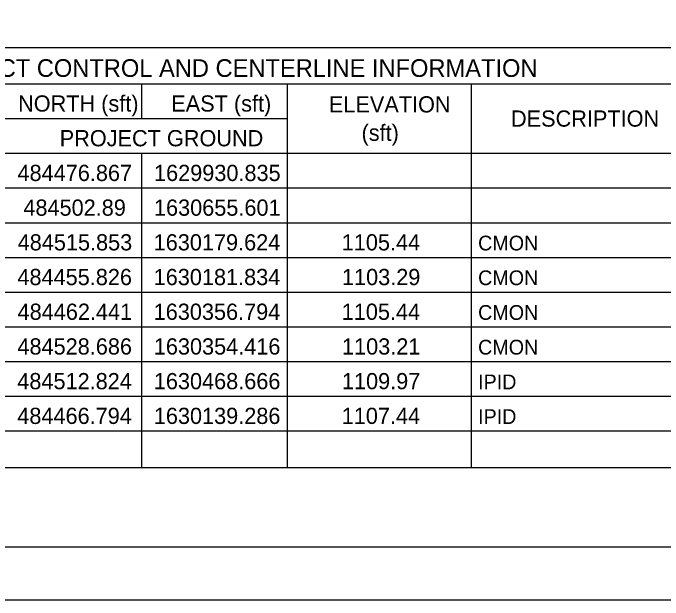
# Model space of a CAD drawing. Extents: x 0 to 34, y 0 to 22.
# Drawn here: x 24.66 to 30.83, y 0 to 5.57 of the extents above; entities that cross this region are included whole.
import ezdxf

# ---------------------------------------------------------------- set-up
doc = ezdxf.new("R2010")
doc.units = 0
for name, color, linetype in [('SH_Border', 7, 'Continuous'), ('SH_Cut_Line', 7, 'Continuous'), ('SH_Data', 7, 'Continuous'), ('SH_Text', 7, 'Continuous')]:
    doc.layers.add(name, color=color, linetype=linetype)

msp = doc.modelspace()

# ---------------------------------------------------------------- linework, layer by layer
at = {"layer": 'SH_Border'}
msp.add_lwpolyline([(1.5, 21.5), (33.5, 21.5), (33.5, 0.5), (1.5, 0.5)], close=True, dxfattribs=at)
at = {"layer": 'SH_Cut_Line'}
msp.add_lwpolyline([(0, 0), (34, 0), (34, 22), (0, 22)], close=True, dxfattribs=at)
at = {"layer": 'SH_Data'}
for p, q in [((20.5456, 5.2448), (30.9386, 5.2448)), ((20.5456, 4.8989), (30.9386, 4.8989)), ((25.8821, 4.8989), (25.8821, 4.5695)), ((27.2656, 4.8989), (27.2656, 1.2589)), ((29.0115, 4.8989), (29.0115, 1.2589)), ((21.2868, 4.5695), (27.2656, 4.5695)), ((20.5456, 4.2401), (30.9386, 4.2401)), ((25.8821, 4.2401), (25.8821, 1.2589)), ((20.5456, 3.9107), (30.9386, 3.9107)), ((20.5456, 3.5812), (30.9386, 3.5812)), ((20.5456, 3.2518), (30.9386, 3.2518)), ((20.5456, 2.9224), (30.9386, 2.9224)), ((20.5456, 2.593), (30.9386, 2.593)), ((20.5456, 2.2636), (30.9386, 2.2636)), ((20.5456, 1.9342), (30.9386, 1.9342)), ((20.5456, 1.6048), (30.9386, 1.6048)), ((20.5456, 1.2589), (30.9386, 1.2589))]:
    msp.add_line(p, q, dxfattribs=at)

# ---------------------------------------------------------------- texts
at = {"layer": 'SH_Text'}
for s, height, p in [('PRIMARY PROJECT CONTROL AND CENTERLINE INFORMATION', 0.168, (22.6895, 4.9648)), ('NORTH (sft)', 0.154, (24.7085, 4.6354)), ('EAST (sft)', 0.154, (26.1633, 4.6354)), ('ELEVATION ', 0.154, (27.6603, 4.6272)), ('DESCRIPTION', 0.154, (29.3901, 4.4925)), ('(sft)', 0.154, (27.9706, 4.3577)), ('PROJECT GROUND', 0.154, (25.1039, 4.306)), ('484476.867', 0.154, (24.7029, 3.9765)), ('1629930.835', 0.154, (25.9996, 3.9765)), ('484502.89', 0.154, (24.7588, 3.6471)), ('1630655.601', 0.154, (25.9991, 3.6471)), ('484515.853', 0.154, (24.7046, 3.3177)), ('1630179.624', 0.154, (25.9963, 3.3177)), ('1105.44', 0.154, (27.7823, 3.3177)), ('CMON', 0.14, (29.0774, 3.3177)), ('484455.826', 0.154, (24.7022, 2.9883)), ('1630181.834', 0.154, (25.9963, 2.9883)), ('1103.29', 0.154, (27.7847, 2.9883)), ('CMON', 0.14, (29.0774, 2.9883)), ('484462.441', 0.154, (24.7038, 2.6589)), ('1630356.794', 0.154, (25.9963, 2.6589)), ('1105.44', 0.154, (27.7823, 2.6589)), ('CMON', 0.14, (29.0774, 2.6589)), ('484528.686', 0.154, (24.7022, 2.3295)), ('1630354.416', 0.154, (25.9975, 2.3295)), ('1103.21', 0.154, (27.7851, 2.3295)), ('CMON', 0.14, (29.0774, 2.3295)), ('484512.824', 0.154, (24.701, 2.0001)), ('1630468.666', 0.154, (25.9975, 2.0001)), ('1109.97', 0.154, (27.7842, 2.0001)), ('IPID', 0.14, (29.0774, 2.0001)), ('484466.794', 0.154, (24.701, 1.6707)), ('1630139.286', 0.154, (25.9975, 1.6707)), ('1107.44', 0.154, (27.7823, 1.6707)), ('IPID', 0.14, (29.0774, 1.6707))]:
    msp.add_text(s, height=height, dxfattribs=at).set_placement(p)

doc.saveas('drawing.dxf')
